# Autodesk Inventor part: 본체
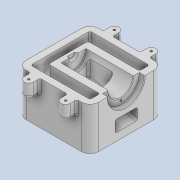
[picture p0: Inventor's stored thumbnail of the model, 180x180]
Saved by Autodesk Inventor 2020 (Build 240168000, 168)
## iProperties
Created: 2022-03
Part Number: 본체
Material: 일반
Document SubType Name: Modeling
Designer: Administrator
Density: 1 g/cm^3
Appearance: 기본값
Mass: 379.358 g
Surface Area: 844.699 cm^2
Volume: 379.358 cm^3
Author: Administrator
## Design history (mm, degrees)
sketch "스케치1"
  geometry: L1 (-55, 55)-(55, 55); L2 (55, 55)-(55, -55); L3 (55, -55)-(-55, -55); L4 (-55, -55)-(-55, 55); L5 (-55, 55)-(55, -55); L6 (55, 55)-(-55, -55); 1 further point
  constraints: 12 end point, 2 midpoint, 2 parallel, 1 horizontal, 1 perpendicular
  dimensions: "d0" = 110 distance of L1.end L2.end; "d1" = 110 distance of L2.end L3.end
extrude "돌출1" new body sketch "스케치1" distance "d2" = 65; taper "d3" = 0 deg
fillet "모깎기1" dims "d4" = 13
sketch "스케치2"
  geometry: L1 (-55, 42)-(-55, -42) reference; L2 (-42, -55)-(42, -55) reference; L3 (55, -42)-(55, 42) reference; L4 (42, 55)-(-42, 55) reference; L5 (-45, -45)-(45, -45); L6 (45, -45)-(45, -30); L7 (45, -30)-(-33, -30); L8 (-33, -30)-(-33, 30); L9 (-33, 30)-(45, 30); L10 (45, 30)-(45, 45); L11 (45, 45)-(-45, 45); L12 (-45, 45)-(-45, -45); 2 further points
  constraints: 16 end point, 6 perpendicular, 2 point on line, 1 horizontal, 1 horizontal alignment, 1 midpoint
  dimensions: "d5" = 10 distance between parallel lines of L12 L1; "d6" = 10 distance between parallel lines of L4 L11; "d7" = 10 distance between parallel lines of L2 L5; "d8" = 10 distance between parallel lines of L3 L10; "d9" = 60 distance of L7.end L8.end; "d10" = 22 distance between parallel lines of L8 L1
extrude "돌출2" cut sketch "스케치2" extent not by distance; stored distance "d11" = 0; taper "d12" = 0 deg
fillet "모깎기2" dims "d13" = 3
sketch "스케치3"
  geometry: L1 (0, 65)-(84, 65) reference; C1 r 28 at (42, 65); C2 r 19 at (42, 65); 1 further point
  constraints: 2 centre point, 1 coincident, 1 midpoint
  dimensions: "d14" = 56 diameter of C1; "d15" = 38 diameter of C2
extrude "돌출3" cut sketch "스케치3" distance "d16" = 8; taper "d17" = 0 deg
extrude "돌출4" cut sketch "스케치3" distance "d18" = 80; taper "d19" = 0 deg
sketch "스케치4"
  geometry: L1 (-25, -19)-(-25, 19) reference; L2 (-25, -7.5)-(-29, -5.191); L3 (-29, -5.191)-(-29, 0); L4 (-32.5, 0)-(-25, 0); A1 r 7.5 centre (-25, 0) between (-25, -7.5) and (-32.5, 0); 1 further point
  constraints: 6 end point, 2 point on circle, 2 point on line, 1 centre point, 1 horizontal, 1 midpoint, 1 vertical
  dimensions: "d20" = 15 diameter of A1; "d22" = 30 deg angle of L2 L4; "d23" = 4 distance between parallel lines of L1 L3
revolve "회전1" sketch "스케치4" stored, may be unused: angle "d24" = 90 deg
fillet "모깎기3" dims "d25" = 1
sketch "스케치5"
  geometry: L1 (-30, 0)-(45, 0) reference; L2 (-33, 30)-(35.578, 11.625); L3 (-33, 0)-(-33, 65) reference; L4 (-19, 72.47)-(-19, 31.425); L5 (19, 38.843)-(19, 72.47); L6 (19, 72.47)-(-19, 72.47); L7 (55, 65)-(55, 37) reference; L8 (19, 38.843)-(69.602, 25.284); L9 (-19, 31.425)-(65.202, 8.863); L10 (65.202, 8.863)-(69.602, 25.284); 2 further points
  constraints: 14 end point, 2 perpendicular, 1 parallel, 1 point on line, 1 vertical
  dimensions: "d27" = 30 distance from line of L1 L2.start; "d28" = 75 deg angle of L3 L2; "d30" = 38 distance of L5.end L4.start; "d31" = 36 distance between parallel lines of L7 L5; "d34" = 5 distance between parallel lines of L2 L9; "d35" = 17 distance between parallel lines of L9 L8
extrude "돌출5" cut sketch "스케치5" stored distance "d32" = 34; taper "d33" = 0 deg
sketch "스케치6"
  geometry: L1 (-33, 30)-(45, 9.1); L2 (-33, 0)-(-33, 65) reference; L3 (-42, 0)-(-55, 0) reference; L4 (45, 9.1)-(45, 0); L5 (45, 0)-(-33, 0); L6 (55, 65)-(55, 0) reference; L7 (55, 0)-(42, 0) reference; L8 (-33, 30)-(-33, 0); 1 further point
  constraints: 8 end point, 2 collinear, 1 perpendicular, 1 point on line, 1 vertical
  dimensions: "d36" = 75 deg angle of L2 L1; "d37" = 30 distance from line of L3 L1.start; "d39" = 10 distance between parallel lines of L6 L4
extrude "돌출6" cut sketch "스케치6" stored distance "d40" = 62; taper "d41" = 0 deg
extrude "돌출7" cut sketch "스케치6" stored distance "d42" = 62; taper "d43" = 0 deg
fillet "모깎기5" dims "d45" = 3
chamfer "모따기1" distance "d46" = 1; stored, may be unused: second distance "d47" = 2, angle "d48" = 45 deg
fillet "모깎기6" dims "d49" = 3
fillet "모깎기7" dims "d50" = 3
fillet "모깎기8" dims "d51" = 3
sketch "스케치7"
  geometry: L1 (-55, 42)-(-55, -42) reference; L2 (-42, -55)-(42, -55) reference; L3 (-35, -65)-(-35, -47.597); L4 (-21, -65)-(-21, -47.597); L5 (-35, -47.597)-(-21, -47.597); L6 (-35, 65)-(-35, 50.14); L7 (-35, 50.14)-(-21, 50.14); L8 (-21, 50.14)-(-21, 65); L9 (21, -65)-(21, -49.94); L10 (21, -49.94)-(35, -49.94); L11 (35, -49.94)-(35, -65); L12 (35, 65)-(35, 49); L13 (21, 65)-(21, 49); L14 (21, 49)-(35, 49); A1 r 7 centre (-28, -65) between (-35, -65) and (-21, -65); A2 r 7 centre (-28, 65) between (-35, 65) and (-21, 65); A3 r 7 centre (28, -65) between (21, -65) and (35, -65); A4 r 7 centre (28, 65) between (35, 65) and (21, 65); 1 further point
  constraints: 24 end point, 8 point on circle, 8 tangent, 4 centre point, 4 perpendicular, 4 vertical, 2 horizontal, 2 point on line, 2 vertical alignment
  dimensions: "d52" = 14 diameter of A1; "d53" = 27 distance from line of A1.centre L1; "d54" = 14 diameter of A2; "d55" = 130 distance of A1.centre A2.centre; "d56" = 65 vertical distance of point (0, 0) A1.centre; "d57" = 14 diameter of A3; "d58" = 14 diameter of A4; "d59" = 130 distance of A3.centre A4.centre; "d60" = 56 distance of A3.centre A1.centre; "d61" = 65 vertical distance of point (0, 0) A3.centre
extrude "돌출8" join sketch "스케치7" distance "d62" = 20; taper "d63" = 0 deg
fillet "모깎기9" dims "d64" = 3
fillet "모깎기10" dims "d65" = 3
sketch "스케치8"
  geometry: A1 r 7 centre (28, 65) between (35, 65) and (21, 65) reference; A2 r 7 centre (-28, 65) between (-21, 65) and (-35, 65) reference; A3 r 7 centre (28, -65) between (21, -65) and (35, -65) reference; A4 r 7 centre (-28, -65) between (-35, -65) and (-21, -65) reference; 5 further points
  constraints: 4 coincident
hole "구멍1" sketch "스케치8" at (28, 65), (-28, 65), (28, -65), (-28, -65) diameter "d66" = 3.242; stored, may be unused: countersink angle "d70" = 90 deg, drill point angle "d72" = 118 deg; dims "d67" = 9, "d68" = 4, "d69" = 2, "d71" = 11
sketch "스케치9" dims "d73" = 46
  geometry: A1 r 20 centre (42, 65) between (22, 65) and (62, 65) reference; A2 r 28 centre (42, 65) between (14, 65) and (70, 65) reference; 3 further points
  constraints: 2 vertical alignment, 1 coincident, 2 other
hole "구멍2" sketch "스케치9" at (42, 42) diameter "d74" = 3.242; stored, may be unused: countersink angle "d78" = 90 deg, drill point angle "d80" = 118 deg; dims "d75" = 9, "d76" = 4, "d77" = 2, "d79" = 11
sketch "스케치10"
  geometry: L1 (0, 0)-(84, 0) reference; L2 (-13, 65)-(-13, 0) reference; 2 further points
  constraints: 1 other
  dimensions: "d81" = 20 distance from line of point (42, 20) L1; "d82" = 55 distance from line of point (42, 20) L2
feature "엠보싱1" sketch "스케치10" dims "d0" = 110, "d1" = 110, "d83" = 0.5, "d84" = 0
node "솔리드1"
feature "A9D066F2-1C7D-4E18-AEED-F7BC21143FA4" dims "d66" = 3.242, "d67" = 9, "d68" = 4, "d69" = 2, "d70" = 90 deg, "d71" = 11, "d72" = 118 deg
